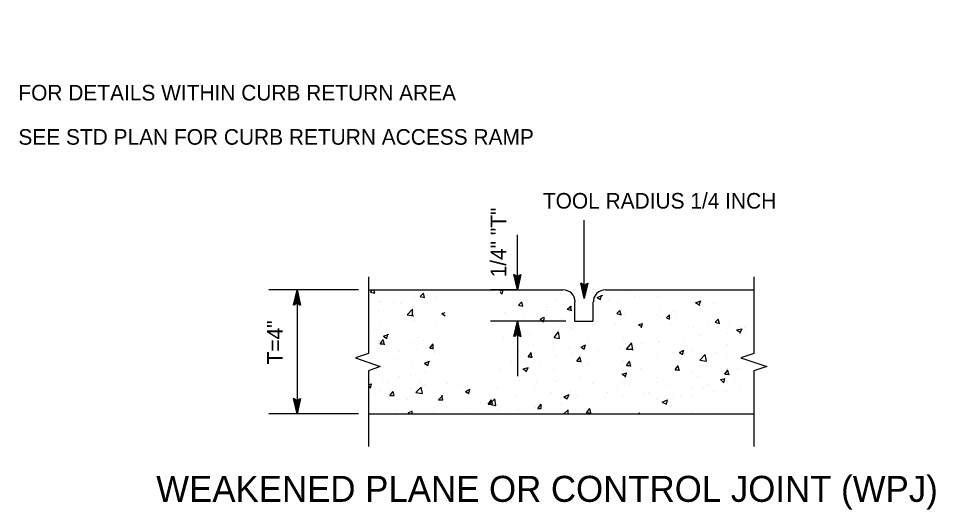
# Model space of a CAD drawing. Extents: x -118779 to -116979, y -104389 to -102939.
# Drawn here: x -118463.7 to -118111.5, y -103361.3 to -103172.4 of the extents above; entities that cross this region are included whole.
import ezdxf

# ---------------------------------------------------------------- set-up
doc = ezdxf.new("R2010")
doc.units = 0
for name, color, linetype in [('G-MARK', 7, 'Continuous'), ('G-TEXT', 7, 'Continuous'), ('Misc CnstDet(22)', 7, 'Continuous')]:
    doc.layers.add(name, color=color, linetype=linetype)

msp = doc.modelspace()

# ---------------------------------------------------------------- linework, layer by layer
at = {"layer": 'G-MARK'}
for p, q in [((-118246.37, -103280.1), (-118246.37, -103249.98)), ((-118272.08, -103276.78), (-118272.08, -103255.63)), ((-118333.05, -103276.78), (-118367.48, -103276.78)), ((-118356.7, -103276.78), (-118356.7, -103324.48)), ((-118253.42, -103288.81), (-118282.45, -103288.81)), ((-118272.08, -103288.81), (-118272.08, -103309.96)), ((-118333.05, -103324.48), (-118367.48, -103324.48))]:
    msp.add_line(p, q, dxfattribs=at)
at = {"layer": 'G-TEXT'}
for points in [[(-118270.77, -103270.88), (-118272.08, -103276.78), (-118273.39, -103270.87), (-118273.04, -103271.09), (-118272.09, -103275.41), (-118271.11, -103271.08), (-118271.46, -103271.29), (-118272.08, -103274.06), (-118272.7, -103271.29), (-118272.35, -103271.51), (-118272.08, -103272.7), (-118271.81, -103271.5), (-118272.08, -103271.66), (-118273.39, -103270.87), (-118272.08, -103271.66)], [(-118245.05, -103274.19), (-118246.37, -103280.1), (-118247.68, -103274.19), (-118247.33, -103274.4), (-118246.37, -103278.73), (-118245.4, -103274.4), (-118245.75, -103274.61), (-118246.37, -103277.38), (-118246.98, -103274.61), (-118246.63, -103274.82), (-118246.37, -103276.02), (-118246.1, -103274.82), (-118246.37, -103274.98), (-118247.68, -103274.19), (-118246.37, -103274.98)], [(-118358.01, -103282.69), (-118356.7, -103276.78), (-118355.39, -103282.69), (-118355.74, -103282.48), (-118356.69, -103278.15), (-118357.67, -103282.48), (-118357.32, -103282.27), (-118356.7, -103279.5), (-118356.08, -103282.27), (-118356.43, -103282.06), (-118356.7, -103280.86), (-118356.97, -103282.06), (-118356.7, -103281.9), (-118355.39, -103282.69), (-118356.7, -103281.9)], [(-118273.4, -103294.71), (-118272.08, -103288.81), (-118270.77, -103294.71), (-118271.12, -103294.5), (-118272.08, -103290.18), (-118273.05, -103294.51), (-118272.7, -103294.3), (-118272.09, -103291.53), (-118271.47, -103294.29), (-118271.82, -103294.08), (-118272.09, -103292.89), (-118272.36, -103294.09), (-118272.08, -103293.93), (-118270.77, -103294.71), (-118272.08, -103293.93)], [(-118355.38, -103318.57), (-118356.7, -103324.48), (-118358.01, -103318.57), (-118357.66, -103318.78), (-118356.7, -103323.11), (-118355.73, -103318.78), (-118356.08, -103318.99), (-118356.69, -103321.76), (-118357.31, -103318.99), (-118356.96, -103319.2), (-118356.69, -103320.4), (-118356.42, -103319.2), (-118356.7, -103319.36), (-118358.01, -103318.57), (-118356.7, -103319.36)]]:
    msp.add_lwpolyline(points, close=True, dxfattribs=at)
at = {"layer": 'Misc CnstDet(22)'}
for p, q in [((-118329.32, -103276.78), (-118254.66, -103276.78)), ((-118329.32, -103276.78), (-118329.32, -103276.78)), ((-118328.49, -103277.61), (-118327.66, -103276.78)), ((-118328.49, -103277.61), (-118326.83, -103278.03)), ((-118326.83, -103278.03), (-118327.25, -103276.78)), ((-118311.49, -103279.68), (-118311.49, -103279.68)), ((-118309.41, -103279.27), (-118308.17, -103278.03)), ((-118309.41, -103279.27), (-118309.41, -103279.27)), ((-118309.41, -103279.27), (-118307.75, -103279.68)), ((-118307.75, -103279.68), (-118308.17, -103278.03)), ((-118303.19, -103279.68), (-118303.19, -103279.68)), ((-118272.5, -103276.78), (-118282.45, -103276.78)), ((-118278.72, -103277.2), (-118277.48, -103276.78)), ((-118278.72, -103277.61), (-118277.89, -103278.44)), ((-118277.89, -103278.44), (-118277.48, -103276.78)), ((-118272.08, -103276.78), (-118272.08, -103276.78)), ((-118268.77, -103276.78), (-118268.77, -103276.78)), ((-118241.39, -103279.68), (-118239.32, -103278.85)), ((-118241.39, -103279.68), (-118240.15, -103280.51)), ((-118240.15, -103280.51), (-118239.73, -103278.85)), ((-118238.07, -103276.78), (-118181.25, -103276.78)), ((-118230.61, -103277.2), (-118230.61, -103277.2)), ((-118227.29, -103279.27), (-118227.29, -103279.27)), ((-118218.16, -103279.27), (-118218.16, -103279.27)), ((-118210.7, -103276.78), (-118210.7, -103276.78)), ((-118325.17, -103281.34), (-118325.17, -103281.34)), ((-118324.76, -103281.76), (-118324.76, -103281.76)), ((-118319.78, -103281.76), (-118319.78, -103281.76)), ((-118316.88, -103282.17), (-118316.88, -103282.17)), ((-118302.78, -103283), (-118302.78, -103283)), ((-118271.67, -103282.59), (-118270.43, -103281.34)), ((-118271.67, -103282.59), (-118270.01, -103283)), ((-118271.25, -103283), (-118271.25, -103283)), ((-118270.01, -103283), (-118270.43, -103281.34)), ((-118260.47, -103283.42), (-118260.47, -103283.42)), ((-118257.57, -103280.93), (-118257.57, -103280.93)), ((-118253.01, -103284.25), (-118251.35, -103283)), ((-118251.35, -103284.66), (-118251.76, -103283)), ((-118250.1, -103281.34), (-118250.1, -103288.81)), ((-118243.05, -103281.34), (-118243.05, -103288.81)), ((-118237.24, -103280.51), (-118237.24, -103280.51)), ((-118233.51, -103281.76), (-118233.51, -103281.76)), ((-118204.06, -103282.59), (-118204.06, -103282.59)), ((-118203.65, -103281.76), (-118201.57, -103280.93)), ((-118203.65, -103281.76), (-118201.99, -103282.59)), ((-118202.4, -103282.59), (-118201.57, -103280.93)), ((-118196.6, -103282.17), (-118196.6, -103282.17)), ((-118190.38, -103280.51), (-118190.38, -103280.51)), ((-118184.15, -103283), (-118184.15, -103283)), ((-118325.59, -103285.08), (-118325.59, -103285.08)), ((-118314.39, -103286.32), (-118312.32, -103284.25)), ((-118314.39, -103286.32), (-118311.9, -103286.74)), ((-118312.32, -103286.74), (-118312.32, -103284.25)), ((-118311.49, -103285.91), (-118311.49, -103285.91)), ((-118301.12, -103285.91), (-118299.87, -103285.49)), ((-118301.12, -103285.91), (-118299.87, -103286.74)), ((-118299.87, -103286.74), (-118299.87, -103286.74)), ((-118277.06, -103285.49), (-118277.06, -103285.49)), ((-118274.99, -103283.83), (-118274.99, -103283.83)), ((-118270.43, -103284.66), (-118270.43, -103284.66)), ((-118264.2, -103287.15), (-118264.2, -103287.15)), ((-118263.37, -103287.98), (-118261.72, -103287.15)), ((-118260.89, -103284.66), (-118260.89, -103284.66)), ((-118253.01, -103284.25), (-118251.35, -103284.66)), ((-118233.93, -103285.91), (-118232.68, -103284.66)), ((-118233.93, -103285.91), (-118232.27, -103286.32)), ((-118232.27, -103286.32), (-118232.68, -103284.66)), ((-118232.68, -103285.91), (-118232.68, -103285.91)), ((-118231.02, -103285.91), (-118231.02, -103285.91)), ((-118218.58, -103286.32), (-118218.58, -103286.32)), ((-118217.34, -103284.25), (-118217.34, -103284.25)), ((-118217.34, -103287.15), (-118217.34, -103287.15)), ((-118214.85, -103287.56), (-118213.6, -103286.32)), ((-118213.6, -103287.98), (-118213.6, -103286.32)), ((-118211.94, -103285.08), (-118211.94, -103285.08)), ((-118211.11, -103286.32), (-118211.11, -103286.32)), ((-118204.48, -103287.15), (-118204.48, -103287.15)), ((-118201.16, -103285.08), (-118201.16, -103285.08)), ((-118325.17, -103290.47), (-118325.17, -103290.47)), ((-118311.49, -103288.39), (-118311.49, -103288.39)), ((-118310.24, -103290.05), (-118310.24, -103290.05)), ((-118303.61, -103289.22), (-118303.61, -103289.22)), ((-118269.18, -103287.56), (-118269.18, -103287.56)), ((-118263.37, -103287.98), (-118262.13, -103288.81)), ((-118262.13, -103289.22), (-118261.72, -103287.56)), ((-118257.98, -103289.64), (-118257.98, -103289.64)), ((-118255.08, -103287.98), (-118255.08, -103287.98)), ((-118250.1, -103288.81), (-118243.05, -103288.81)), ((-118250.1, -103288.81), (-118250.1, -103288.81)), ((-118242.64, -103290.05), (-118242.64, -103290.05)), ((-118241.39, -103288.81), (-118241.39, -103288.81)), ((-118234.34, -103289.64), (-118234.34, -103289.64)), ((-118227.29, -103287.56), (-118227.29, -103287.56)), ((-118227.29, -103289.22), (-118227.29, -103289.22)), ((-118225.63, -103290.05), (-118223.97, -103289.64)), ((-118225.63, -103290.05), (-118224.39, -103290.88)), ((-118224.39, -103291.3), (-118223.97, -103289.64)), ((-118214.85, -103287.56), (-118213.6, -103287.98)), ((-118213.19, -103290.05), (-118213.19, -103290.05)), ((-118199.09, -103290.47), (-118199.09, -103290.47)), ((-118196.18, -103289.22), (-118194.94, -103287.98)), ((-118196.18, -103289.22), (-118194.52, -103289.64)), ((-118194.52, -103289.64), (-118194.94, -103287.98)), ((-118190.79, -103289.22), (-118190.79, -103289.22)), ((-118190.38, -103287.56), (-118190.38, -103287.56)), ((-118326.83, -103292.13), (-118326.83, -103292.13)), ((-118323.51, -103294.62), (-118321.44, -103293.79)), ((-118322.27, -103295.45), (-118321.86, -103293.79)), ((-118271.25, -103291.71), (-118271.25, -103291.71)), ((-118267.52, -103293.79), (-118267.52, -103293.79)), ((-118257.98, -103292.96), (-118257.98, -103292.96)), ((-118257.98, -103295.03), (-118256.32, -103292.96)), ((-118255.91, -103295.45), (-118256.32, -103292.96)), ((-118250.93, -103291.71), (-118250.93, -103291.71)), ((-118244.3, -103290.88), (-118244.3, -103290.88)), ((-118217.75, -103292.96), (-118217.75, -103292.96)), ((-118204.48, -103291.3), (-118204.48, -103291.3)), ((-118201.99, -103294.2), (-118201.99, -103294.2)), ((-118191.21, -103293.37), (-118191.21, -103293.37)), ((-118187.89, -103292.13), (-118185.81, -103291.71)), ((-118187.89, -103292.13), (-118186.64, -103292.96)), ((-118186.64, -103291.3), (-118186.64, -103291.3)), ((-118186.64, -103293.37), (-118185.81, -103291.71)), ((-118184.98, -103291.3), (-118184.98, -103291.3)), ((-118184.57, -103292.54), (-118184.57, -103292.54)), ((-118325.59, -103297.52), (-118325.59, -103297.52)), ((-118324.76, -103297.52), (-118323.51, -103295.86)), ((-118324.76, -103297.52), (-118323.1, -103297.52)), ((-118323.51, -103294.62), (-118322.27, -103295.45)), ((-118323.1, -103297.93), (-118323.51, -103296.27)), ((-118322.27, -103295.45), (-118322.27, -103295.45)), ((-118311.9, -103297.1), (-118311.9, -103297.1)), ((-118310.24, -103295.03), (-118310.24, -103295.03)), ((-118308.17, -103296.27), (-118308.17, -103296.27)), ((-118305.68, -103299.18), (-118304.44, -103297.52)), ((-118277.48, -103295.03), (-118277.48, -103295.03)), ((-118273.33, -103295.45), (-118273.33, -103295.45)), ((-118257.98, -103295.03), (-118255.91, -103295.45)), ((-118245.12, -103296.69), (-118245.12, -103296.69)), ((-118231.44, -103295.03), (-118231.44, -103295.03)), ((-118230.19, -103299.59), (-118228.12, -103297.1)), ((-118227.7, -103300.01), (-118228.12, -103297.52)), ((-118224.39, -103297.52), (-118224.39, -103297.52)), ((-118217.75, -103296.69), (-118217.75, -103296.69)), ((-118217.34, -103296.69), (-118217.34, -103296.69)), ((-118207.8, -103295.45), (-118207.8, -103295.45)), ((-118325.59, -103299.18), (-118325.59, -103299.18)), ((-118317.29, -103300.42), (-118317.29, -103300.42)), ((-118310.66, -103299.59), (-118310.66, -103299.59)), ((-118305.68, -103299.18), (-118304.44, -103299.18)), ((-118304.44, -103299.59), (-118304.44, -103297.93)), ((-118304.02, -103300.84), (-118304.02, -103300.84)), ((-118300.7, -103298.35), (-118300.7, -103298.35)), ((-118271.67, -103300.42), (-118271.67, -103300.42)), ((-118267.94, -103302.5), (-118266.69, -103300.84)), ((-118266.69, -103302.91), (-118266.69, -103301.25)), ((-118265.86, -103297.93), (-118265.86, -103297.93)), ((-118258.4, -103298.35), (-118258.4, -103298.35)), ((-118252.18, -103298.76), (-118252.18, -103298.76)), ((-118250.93, -103301.25), (-118250.93, -103301.25)), ((-118247.61, -103298.76), (-118245.95, -103297.93)), ((-118247.61, -103298.76), (-118246.37, -103299.59)), ((-118246.37, -103299.59), (-118245.95, -103297.93)), ((-118240.98, -103300.01), (-118240.98, -103300.01)), ((-118238.07, -103299.18), (-118238.07, -103299.18)), ((-118232.68, -103299.18), (-118232.68, -103299.18)), ((-118230.19, -103299.59), (-118227.7, -103299.59)), ((-118223.97, -103299.59), (-118223.97, -103299.59)), ((-118209.87, -103300.84), (-118208.21, -103300.01)), ((-118209.87, -103300.42), (-118209.87, -103300.42)), ((-118209.87, -103300.84), (-118208.63, -103301.67)), ((-118208.63, -103301.67), (-118208.21, -103300.01)), ((-118204.89, -103300.01), (-118204.89, -103300.01)), ((-118195.77, -103300.84), (-118195.77, -103300.84)), ((-118191.21, -103297.93), (-118191.21, -103297.93)), ((-118319.37, -103303.33), (-118319.37, -103303.33)), ((-118307.75, -103304.98), (-118305.68, -103304.16)), ((-118306.51, -103305.81), (-118306.09, -103304.57)), ((-118274.16, -103304.16), (-118274.16, -103304.16)), ((-118267.94, -103302.5), (-118266.28, -103302.5)), ((-118263.37, -103304.57), (-118263.37, -103304.57)), ((-118257.57, -103302.08), (-118257.57, -103302.08)), ((-118249.27, -103304.16), (-118248.03, -103302.5)), ((-118249.27, -103304.16), (-118247.61, -103304.16)), ((-118248.03, -103302.08), (-118248.03, -103302.08)), ((-118247.61, -103304.57), (-118248.03, -103302.91)), ((-118231.44, -103303.74), (-118231.44, -103303.74)), ((-118230.19, -103305.81), (-118228.95, -103304.16)), ((-118228.53, -103306.23), (-118228.95, -103304.57)), ((-118218.16, -103301.67), (-118218.16, -103301.67)), ((-118201.99, -103303.74), (-118199.92, -103301.67)), ((-118201.99, -103303.74), (-118199.5, -103304.16)), ((-118199.5, -103304.16), (-118199.92, -103301.67)), ((-118198.26, -103303.74), (-118198.26, -103303.74)), ((-118191.62, -103302.91), (-118191.62, -103302.91)), ((-118326, -103307.89), (-118326, -103307.89)), ((-118312.32, -103305.81), (-118312.32, -103305.81)), ((-118307.75, -103304.98), (-118306.51, -103305.81)), ((-118278.72, -103307.47), (-118278.72, -103307.47)), ((-118270.01, -103307.06), (-118267.94, -103306.64)), ((-118270.01, -103307.06), (-118268.77, -103307.89)), ((-118268.77, -103308.3), (-118267.94, -103306.64)), ((-118258.4, -103307.47), (-118258.4, -103307.47)), ((-118245.12, -103305.4), (-118245.12, -103305.4)), ((-118231.44, -103307.89), (-118231.44, -103307.89)), ((-118230.19, -103305.81), (-118228.53, -103305.81)), ((-118224.8, -103307.06), (-118224.8, -103307.06)), ((-118214.85, -103305.81), (-118214.85, -103305.81)), ((-118211.53, -103307.47), (-118210.28, -103305.81)), ((-118211.53, -103307.47), (-118209.87, -103307.47)), ((-118209.87, -103307.89), (-118210.28, -103306.23)), ((-118192.45, -103309.13), (-118191.21, -103307.47)), ((-118191.21, -103307.06), (-118191.21, -103307.06)), ((-118190.79, -103309.55), (-118191.21, -103307.89)), ((-118187.47, -103307.06), (-118187.47, -103307.06)), ((-118327.25, -103309.13), (-118327.25, -103309.13)), ((-118323.93, -103310.79), (-118323.93, -103310.79)), ((-118317.29, -103309.96), (-118317.29, -103309.96)), ((-118313.15, -103309.55), (-118313.15, -103309.55)), ((-118307.34, -103308.72), (-118307.34, -103308.72)), ((-118272.08, -103309.13), (-118272.08, -103309.13)), ((-118271.25, -103311.62), (-118271.25, -103311.62)), ((-118257.98, -103311.62), (-118257.98, -103311.62)), ((-118248.03, -103310.38), (-118248.03, -103310.38)), ((-118231.85, -103309.13), (-118230.19, -103308.72)), ((-118231.85, -103309.13), (-118230.61, -103309.96)), ((-118230.61, -103310.38), (-118230.19, -103308.72)), ((-118218.16, -103310.38), (-118218.16, -103310.38)), ((-118204.89, -103308.72), (-118204.89, -103308.72)), ((-118202.82, -103309.96), (-118202.82, -103309.96)), ((-118194.11, -103311.21), (-118192.45, -103310.79)), ((-118194.11, -103311.21), (-118192.86, -103312.45)), ((-118192.86, -103312.45), (-118192.45, -103310.79)), ((-118192.45, -103309.13), (-118190.79, -103309.13)), ((-118329.32, -103313.28), (-118328.08, -103312.87)), ((-118329.32, -103313.69), (-118328.49, -103314.52)), ((-118328.49, -103314.52), (-118328.08, -103312.87)), ((-118324.76, -103315.35), (-118324.76, -103315.35)), ((-118321.86, -103312.45), (-118321.86, -103312.45)), ((-118312.73, -103314.52), (-118312.73, -103314.52)), ((-118311.07, -103316.18), (-118309, -103314.11)), ((-118309.41, -103312.45), (-118309.41, -103312.45)), ((-118308.58, -103316.6), (-118309, -103314.11)), ((-118307.75, -103313.28), (-118307.75, -103313.28)), ((-118299.04, -103312.87), (-118299.04, -103312.87)), ((-118293.65, -103313.69), (-118293.65, -103313.69)), ((-118291.99, -103315.77), (-118290.33, -103314.94)), ((-118290.75, -103316.6), (-118290.33, -103314.94)), ((-118281.21, -103314.52), (-118281.21, -103314.52)), ((-118279.55, -103314.52), (-118279.55, -103314.52)), ((-118265.45, -103314.94), (-118265.45, -103314.94)), ((-118264.62, -103312.45), (-118264.62, -103312.45)), ((-118257.15, -103312.04), (-118257.15, -103312.04)), ((-118245.54, -103314.52), (-118245.54, -103314.52)), ((-118243.05, -103312.87), (-118243.05, -103312.87)), ((-118233.51, -103314.94), (-118233.51, -103314.94)), ((-118231.85, -103312.45), (-118231.85, -103312.45)), ((-118228.95, -103313.28), (-118228.95, -103313.28)), ((-118218.16, -103312.45), (-118218.16, -103312.45)), ((-118214.85, -103313.69), (-118214.85, -103313.69)), ((-118205.31, -103314.11), (-118205.31, -103314.11)), ((-118200.74, -103314.52), (-118200.74, -103314.52)), ((-118198.67, -103313.28), (-118198.67, -103313.28)), ((-118188.72, -103312.04), (-118188.72, -103312.04)), ((-118186.64, -103314.94), (-118186.64, -103314.94)), ((-118326.42, -103316.6), (-118326.42, -103316.6)), ((-118321.03, -103317.43), (-118319.78, -103315.77)), ((-118321.03, -103317.43), (-118319.37, -103317.43)), ((-118319.37, -103317.43), (-118319.78, -103315.77)), ((-118311.07, -103316.18), (-118308.58, -103316.6)), ((-118302.36, -103319.09), (-118300.7, -103317.43)), ((-118300.7, -103319.09), (-118301.12, -103317.43)), ((-118297.8, -103317.01), (-118297.8, -103317.01)), ((-118291.99, -103315.77), (-118290.75, -103316.6)), ((-118291.16, -103315.77), (-118291.16, -103315.77)), ((-118282.87, -103320.75), (-118280.79, -103318.67)), ((-118280.38, -103321.16), (-118280.79, -103318.67)), ((-118272.5, -103317.84), (-118272.5, -103317.84)), ((-118258.81, -103316.18), (-118258.81, -103316.18)), ((-118254.25, -103317.84), (-118252.18, -103317.01)), ((-118254.25, -103317.84), (-118253.01, -103318.67)), ((-118253.01, -103318.67), (-118252.18, -103317.01)), ((-118251.76, -103315.77), (-118251.76, -103315.77)), ((-118248.86, -103317.84), (-118248.86, -103317.84)), ((-118238.49, -103318.67), (-118238.49, -103318.67)), ((-118237.66, -103316.18), (-118237.66, -103316.18)), ((-118231.85, -103317.43), (-118231.85, -103317.43)), ((-118223.56, -103316.6), (-118223.56, -103316.6)), ((-118221.9, -103316.18), (-118221.9, -103316.18)), ((-118211.94, -103318.26), (-118211.94, -103318.26)), ((-118209.45, -103317.43), (-118209.45, -103317.43)), ((-118205.31, -103317.43), (-118205.31, -103317.43)), ((-118196.6, -103315.77), (-118196.6, -103315.77)), ((-118195.35, -103317.84), (-118195.35, -103317.84)), ((-118191.62, -103315.77), (-118191.62, -103315.77)), ((-118324.34, -103320.33), (-118324.34, -103320.33)), ((-118314.39, -103319.09), (-118314.39, -103319.09)), ((-118302.36, -103319.09), (-118300.7, -103319.09)), ((-118299.46, -103321.58), (-118299.46, -103321.58)), ((-118286.19, -103319.92), (-118286.19, -103319.92)), ((-118283.28, -103320.75), (-118282.04, -103319.09)), ((-118283.28, -103320.75), (-118281.62, -103320.75)), ((-118282.87, -103320.75), (-118280.38, -103321.16)), ((-118281.62, -103320.75), (-118282.04, -103319.09)), ((-118265.03, -103321.99), (-118265.03, -103321.99)), ((-118264.2, -103320.33), (-118264.2, -103320.33)), ((-118264.2, -103322.4), (-118262.96, -103320.75)), ((-118264.2, -103322.4), (-118262.96, -103322.4)), ((-118262.96, -103322.4), (-118262.96, -103320.75)), ((-118255.08, -103320.75), (-118255.08, -103320.75)), ((-118245.54, -103324.06), (-118244.3, -103322.4)), ((-118243.88, -103324.06), (-118244.3, -103322.4)), ((-118232.27, -103321.16), (-118232.27, -103321.16)), ((-118227.29, -103320.75), (-118227.29, -103320.75)), ((-118218.58, -103319.09), (-118218.58, -103319.09)), ((-118216.51, -103319.92), (-118214.43, -103319.09)), ((-118216.51, -103319.92), (-118214.85, -103320.75)), ((-118214.85, -103320.75), (-118214.43, -103319.09)), ((-118195.35, -103322.4), (-118195.35, -103322.4)), ((-118356.7, -103324.48), (-118356.7, -103324.48)), ((-118329.32, -103324.48), (-118181.25, -103324.48)), ((-118329.32, -103324.48), (-118329.32, -103324.48)), ((-118318.54, -103323.23), (-118318.54, -103323.23)), ((-118313.98, -103324.06), (-118312.32, -103323.23)), ((-118313.98, -103324.06), (-118313.56, -103324.48)), ((-118312.73, -103323.23), (-118312.73, -103323.23)), ((-118312.73, -103324.48), (-118312.32, -103323.65)), ((-118304.44, -103323.65), (-118304.44, -103323.65)), ((-118290.33, -103324.06), (-118290.33, -103324.06)), ((-118279.55, -103322.82), (-118279.55, -103322.82)), ((-118271.67, -103322.82), (-118271.67, -103322.82)), ((-118254.25, -103324.48), (-118252.59, -103322.82)), ((-118252.59, -103324.48), (-118252.59, -103322.82)), ((-118245.95, -103323.23), (-118245.95, -103323.23)), ((-118245.54, -103324.06), (-118243.88, -103324.06)), ((-118242.64, -103323.65), (-118242.64, -103323.65)), ((-118225.63, -103324.48), (-118225.22, -103324.06)), ((-118225.22, -103324.48), (-118225.22, -103324.06)), ((-118205.31, -103323.65), (-118205.31, -103323.65)), ((-118192.03, -103324.48), (-118192.03, -103324.48))]:
    msp.add_line(p, q, dxfattribs=at)
for points in [[(-118329.32, -103271.8), (-118329.32, -103301.25), (-118334.3, -103302.91), (-118324.76, -103306.23), (-118329.32, -103307.89), (-118329.32, -103336.92)], [(-118181.25, -103271.8), (-118181.25, -103301.25), (-118186.23, -103302.91), (-118176.27, -103306.23), (-118181.25, -103307.89), (-118181.25, -103336.92)]]:
    msp.add_lwpolyline(points, dxfattribs=at)
for centre, radius, start, end in [((-118457.89, -103252.04), 223.87, 90, 180), ((-118457.89, -103252.04), 209.05, 90, 180), ((-118457.89, -103252.04), 202.47, 90, 180), ((-118254.6, -103281.41), 4.68, 0, 90), ((-118238.23, -103281.41), 4.68, 90, 180)]:
    msp.add_arc(centre, radius, start, end, dxfattribs=at)

# ---------------------------------------------------------------- texts
for s, height, p in [('FOR DETAILS WITHIN CURB RETURN AREA', 6, (-118463.71, -103203.98)), ('SEE STD PLAN FOR CURB RETURN ACCESS RAMP', 6, (-118463.71, -103220.98)), ('TOOL RADIUS 1/4 INCH', 6, (-118262.28, -103245.53)), ('WEAKENED PLANE OR CONTROL JOINT (WPJ)', 10, (-118410.78, -103358.25))]:
    msp.add_text(s, height=height, dxfattribs=at).set_placement(p)
for s, p in [('1/4" "T"', (-118276.36, -103271.98)), ('T=4"', (-118362.18, -103305.42))]:
    msp.add_text(s, height=6, rotation=90, dxfattribs=at).set_placement(p)

doc.saveas('drawing.dxf')
